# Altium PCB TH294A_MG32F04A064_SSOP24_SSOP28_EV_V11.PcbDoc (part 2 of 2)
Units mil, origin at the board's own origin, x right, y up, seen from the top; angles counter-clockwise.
Board outline 4724.41 x 2637.8 mil, 2 copper layers (Top Layer, Bottom Layer); 130 components, 100 nets, 562 pads, 309 vias.
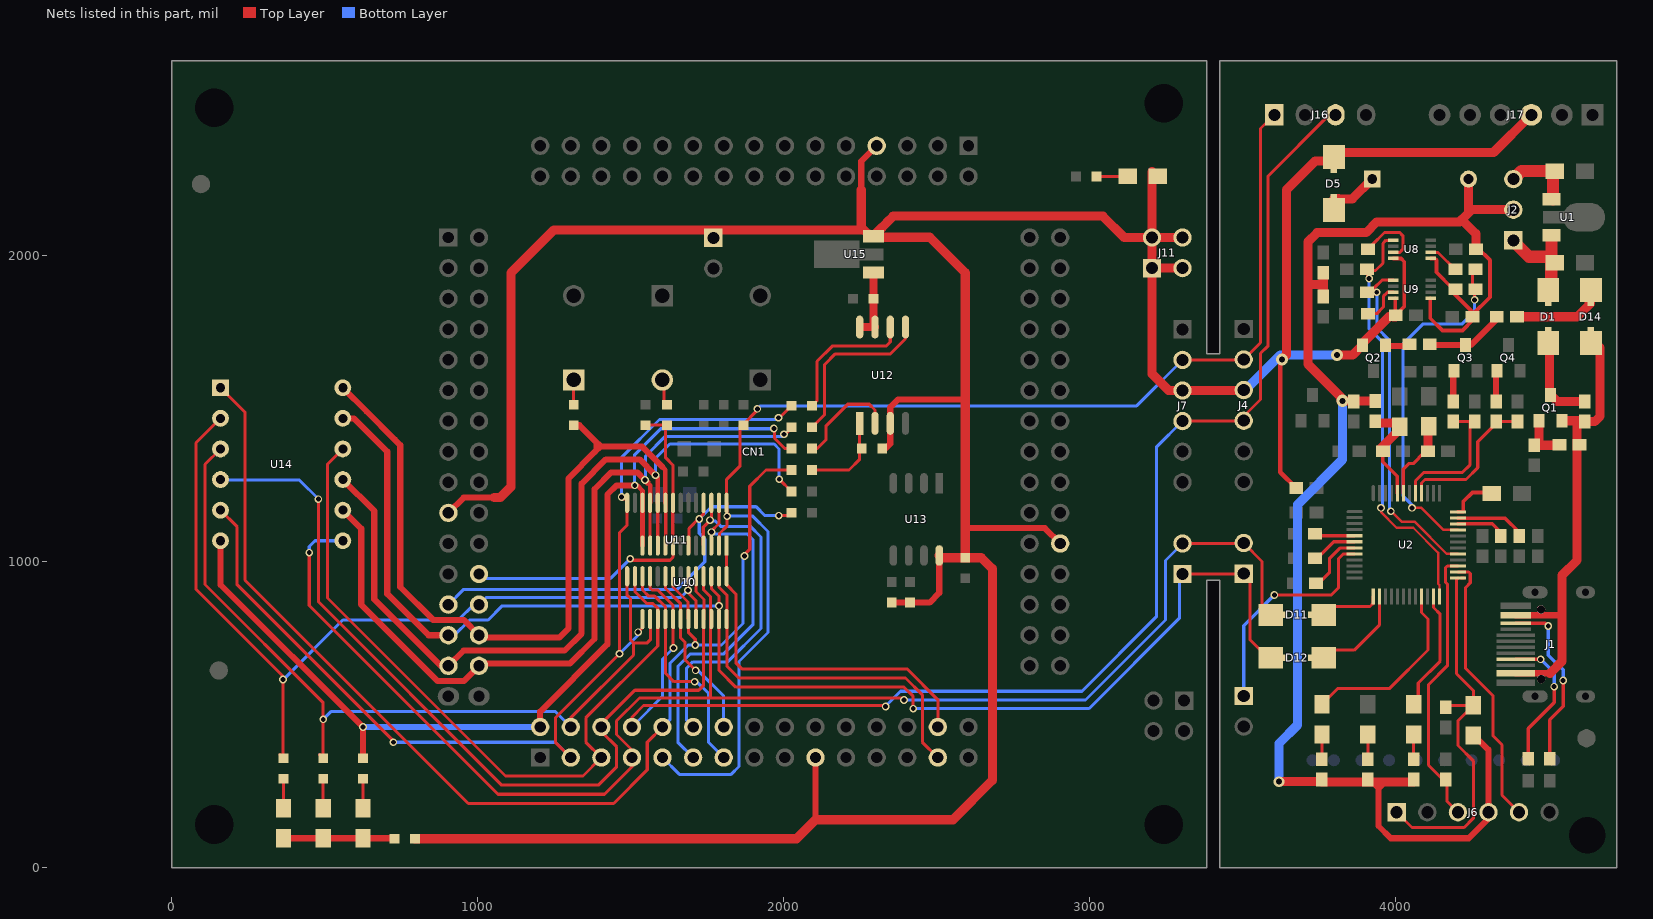
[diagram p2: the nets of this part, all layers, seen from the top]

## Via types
v1: diameter 20, hole 12, Top Layer to Bottom Layer, tented both sides, 221 vias
v2: diameter 25, hole 16, Top Layer to Bottom Layer, tented both sides, 61 vias
v3: diameter 30, hole 12, Top Layer to Bottom Layer, tented both sides, 13 vias
v4: diameter 25, hole 12, Top Layer to Bottom Layer, tented both sides, 6 vias
v5: diameter 40, hole 20, Top Layer to Bottom Layer, tented both sides, 3 vias
v6: diameter 30, hole 16, Top Layer to Bottom Layer, tented both sides, 2 vias
v7: diameter 15, hole 12, Top Layer to Bottom Layer, tented both sides, 1 vias
v8: diameter 35, hole 20, Top Layer to Bottom Layer, tented both sides, 1 vias
v9: diameter 28, hole 16, Top Layer to Bottom Layer, tented both sides, 1 vias

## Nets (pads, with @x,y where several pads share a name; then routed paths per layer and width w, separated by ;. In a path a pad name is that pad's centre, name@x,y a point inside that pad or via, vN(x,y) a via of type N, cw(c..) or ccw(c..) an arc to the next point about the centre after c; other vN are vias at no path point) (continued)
ICP/SWD_SDA: R41.1 R64.1 U2.33 | length 1167.1
  Top Layer w8: v2(4054.92,1176.26) 4085.92,1176.26 4157.82,1104.36 U2.33@4205.42,1104.36
  Top Layer w10: R64.1@4252.92,1966.26 4252.92,1956.26 4252.92,1891.26 4257.92,1886.26 4259.92,1884.26 v2(4259.92,1856.26)
  Bottom Layer w10: 4024.92,1506.26 4024.92,1496.26 ; v2@4052.92,1176.26 4052.92,1188.26 4024.92,1216.26 4024.92,1496.26 ; v2(4259.92,1856.26) 4259.92,1818.26 4219.39,1777.73 4091.39,1777.73 4024.92,1711.26 4024.92,1496.26
MLINK_RXD: CN1.7 D11.2 J5.2 J8.2 U10.22 U11.25 U14.7 | length 4926.9
  Top Layer w10: v2(450,1030) 450,856.91 1066.91,240 1415,240 1504.96,329.96 CN1.7@1504.96,360 1504.96,385.04 1454.41,435.59 1454.41,480 1529.41,555 2387.84,555 v2(2394.41,548.43) ; U11.25@1739.41,962.84 U11.25@1739.41,952.84 1739.41,907.84 1762.41,884.84 1762.41,812.84 1762.41,560 ; J8.2@3304.96,1060 J5.2@3504.96,1060 ; J5.2@3504.96,1061.26 3564.96,1001.26 3564.96,826.26 D11.2@3564.96,811.26
  Bottom Layer w10: v2(450,1030) 450,1050 468.9,1068.9 U14.7@559.92,1068.9 ; v2(2394.41,548.43) 2987.84,548.43 3249.41,810 3249.41,1004.45 J8.2@3304.96,1060
MLINK_TXD: CN1.117 D12.1 J5.1 J8.1 U10.23 U11.26 U14.11 | length 4671.1
  Top Layer w8: J5.1@3504.96,961.26 J5.1@3510.73,955.49
  Top Layer w10: U11.26@1764.41,952.84 1764.41,912.84 1789.41,887.84 v2(1789.41,856) U10.23@1789.41,812.84 1789.41,645 1844.41,590 2394.41,590 2424.41,560 v2(2424.41,520.15) ; J8.1@3304.96,960 J5.1@3504.96,960 ; J5.1@3524.96,959.26 3524.96,746.26 D12.1@3578.35,692.87
  Top Layer w20: U14.11@559.92,1468.9 596.1,1468.9 705,1360 705,1080 ; 705,1183.82 705,1080 ; CN1.117@904.96,760 840,760 705,895 705,1080
  Bottom Layer w10: CN1.117@904.96,775.55 CN1.117@904.96,760 924.41,760 974.41,810 1035,810 1081,856 v2(1789.41,856) ; v2(2424.41,520.15) 2999.56,520.15 3294.41,815 ; 3294.41,880 3294.41,815 ; J8.1@3294.41,949.45 3294.41,815
NetC2_2: C2.2 Q1.1 R5.2 | length 165
  Top Layer w30: R5.2@4454.96,1381.26 R5.2@4469.96,1381.26 ; Q1.1@4469.96,1461.26 R5.2@4469.96,1381.26 ; C2.2@4539.96,1381.26 4536.92,1381.26 R5.2@4469.96,1381.26
NetC6_1: C6.1 C7.2 R10.2 U2.44 | length 332.7
  Top Layer w11: C7.2@3959.92,1361.26 3959.92,1327.26 4007.15,1280.03 U2.44@4007.15,1224.39
  Top Layer w30: R10.2@3949.96,1453.26 4014.92,1453.26 C6.1@4014.92,1442.05 4014.92,1433.26 3953.92,1372.26 C7.2@3953.92,1367.26
NetC8_2: C8.2 C9.1 U2.43 | length 251
  Top Layer w11: U2.43@4026.84,1224.39 4026.84,1303.18 4044.92,1321.26 4058.92,1321.26 4095.42,1357.76 4106.92,1357.76 C8.2@4110.42,1357.76
  Top Layer w30: C8.2@4106.92,1361.26 C9.1@4106.92,1427.31
NetC11_1: C11.1 U2.36 | length 149.7
  Top Layer w12: U2.36@4205.42,1163.42 4222.12,1163.42 4222.12,1195.94 4252.82,1226.65 C11.1@4309.86,1226.65
NetD1_1: D1.1 Q1.3 R1.2 | length 276.4
  Top Layer w30: D1.1@4504.92,1699.65 4504.92,1548.24 Q1.3@4507.96,1545.2 4528.9,1524.26 R1.2@4619.96,1524.26
NetD2_1: D2.1 R6.2 | length 80.8
  Top Layer w10: R6.2@3760.51,354.52 D2.1@3760.51,435.31
NetD3_1: D3.1 R9.2 | length 80.8
  Top Layer w10: R9.2@4060.51,354.52 D3.1@4060.51,435.31
NetD4_1: D4.1 R11.2 | length 80.8
  Top Layer w10: R11.2@3910.51,354.52 D4.1@3910.51,435.31
NetD5_1: D5.1 SW1.1 | length 154.2
  Top Layer w30: D5.1@3799.92,2187.18 3815.85,2187.18 3814.92,2186.26 3859.96,2186.26 SW1.1@3924.96,2251.26
NetD8_1: D8.1 D9.1 D10.1 R58.1 | length 364.8
  Top Layer w20: D8.1@365.67,96.06 D9.1@495.67,96.06 D10.1@625.67,96.06 728.91,96.06 R58.1@730.47,96.06
NetD8_2: D8.2 R54.2 | length 96.5
  Top Layer w10: D8.2@365.67,194.49 R54.2@365.67,290.99
NetD9_2: D9.2 R55.2 | length 96.5
  Top Layer w10: D9.2@495.67,194.49 R55.2@495.67,290.99
NetD10_2: D10.2 R56.2 | length 96.5
  Top Layer w10: D10.2@625.67,194.49 R56.2@625.67,290.99
NetD11_1: D11.1 U2.13 | length 188.6
  Top Layer w10: D11.1@3766.57,854 3917.96,854 3928.41,864.45 U2.13@3928.41,886.91
NetD12_2: D12.2 U2.14 | length 296
  Top Layer w10: D12.2@3779.96,711 3866.06,711 3948.1,793.04 U2.14@3948.1,886.91
NetD13_2: D13.2 R43.2 | length 102.3
  Top Layer w10: R43.2@3023.46,2260 D13.2@3125.75,2260
NetD14_2: D14.2 R17.1 | length 272.5
  Top Layer w30: R17.1@4397.92,1801.26 4594.92,1801.26 D14.2@4639,1845.33 ; D14.2@4628.07,1869.41 D14.2@4639.92,1869.41 ; D14.2@4634,1845.33 D14.2@4634.92,1846.26
NetJ1_A5: J1.A5 R26.1 | length 460.3
  Top Layer w11: J1.A5@4393.76,681.16 v2(4475.51,681.16) ; R26.1@4434.96,356 4434.96,455 4519.96,540 v2@4519.96,592
  Bottom Layer w11: v2(4475.51,681.16) 4519.51,637.16 v2(4519.51,592)
NetJ1_B5: J1.B5 R27.2 | length 582.9
  Top Layer w11: J1.B5@4393.76,799.27 4491.24,799.27 v2(4500.51,790) ; R27.2@4504.96,356 4504.96,483 4548.96,527 v2(4548.96,612)
  Bottom Layer w11: v2(4500.51,790) 4500.51,695 4548.96,646.55 v2(4548.96,612)
NetQ2_1: Q2.1 R18.2 | length 72
  Top Layer w20: Q2.1@3967.92,1705.2 R18.2@4039.92,1705.2
NetQ3_1: Q3.1 R19.2 | length 97.5
  Top Layer w20: R19.2@4189.96,1524.26 Q3.1@4189.96,1621.79
NetQ3_2: Q3.2 R17.2 R18.1 | length 242.2
  Top Layer w20: R18.1@4132.95,1708.23 Q3.2@4230.46,1708.23 4246.89,1708.23 4331.92,1793.26 R17.2@4331.92,1801.26
NetQ4_1: Q4.1 R23.2 | length 97.5
  Top Layer w20: R23.2@4329.96,1524.26 Q4.1@4329.96,1621.79
NetR15_1: R15.1 U2.35 | length 263.6
  Top Layer w12: U2.35@4205.42,1142.73 4234.96,1142.73 ; 4267.22,1142.73 4234.96,1142.73 ; R15.1@4405.51,1084.26 4405.51,1096.26 4359.04,1142.73 4234.96,1142.73
NetR16_1: R16.1 U2.34 | length 163.6
  Top Layer w12: U2.34@4205.42,1124.05 4317.72,1124.05 4345.51,1096.26 R16.1@4345.51,1084.26
NetR29_2: R29.2 U8.7 | length 202.9
  Top Layer w10: R29.2@3924.92,2036.26 3964.92,2076.26 4014.92,2076.26 4024.92,2066.26 4024.92,2021.26 4015.08,2011.42 U8.7@3993.9,2011.42 U8.7@3991.78,2011.42
NetR30_2: R30.2 U9.7 | length 132.5
  Top Layer w10: R30.2@3910.92,1811.26 3939.92,1811.26 3961.42,1832.76 3961.42,1867.76 3975.08,1881.42 U9.7@3993.9,1881.42
NetR59_1: R59.1 SW4.2 | length 80.9
  Top Layer w10: R59.1@1609.41,1513.5 SW4.2@1609.41,1594.41
NetR61_2: R61.2 SW3.1 | length 80.9
  Top Layer w10: R61.2@1314.41,1513.5 SW3.1@1314.41,1594.41
NetR64_2: R64.2 U8.2 | length 108.2
  Top Layer w10: U8.2@4115.94,2011.42 4139.76,2011.42 R64.2@4195.92,1955.26 ; R64.2@4183.42,1969.76 R64.2@4186.92,1966.26
P44: J6.5 U2.26 | length 900.8
  Top Layer w10: U2.26@4205.42,966.57 4240.2,966.57 4245.51,961.26 4245.51,931.26 4230.51,916.26 4230.51,651.26 4320.51,561.26 4320.51,430.26 4349.06,401.71 4349.06,237.16 J6.5@4404.96,181.26
P45: J6.3 R25.1 U2.27 | length 931.6
  Top Layer w10: R25.1@4169.24,291.98 4169.24,288.26 4169.24,216.98 J6.3@4204.96,181.26 ; R25.1@4170.51,293.26 4165.51,293.26 4150.95,293.26 4108.96,335.25 4108.96,598.45 4170.51,660 4170.51,927.26 4163.92,933.85 4163.92,979.67 4170.5,986.25 U2.27@4205.42,986.25 ; J6.3@4206.24,182.54 J6.3@4213.51,175.26
PA0: CN1.114 R59.2 R60.1 U10.8 U11.8 | length 1204
  Top Layer w10: CN1.114@1004.96,960 1017.99,960 CN1.114@1016.2,958.21 ; v2(1499.41,1010) 1499.41,1005 1629.41,1005 1639.41,1015 U10.8@1639.41,1052.84 ; R60.1@1549.41,1446.5 1609.41,1446.5 R59.2@1610,1445.91 ; R59.2@1610,1448.91 1610,1446.5 R59.2@1610,1445.91 ; R59.2@1615,1446.5 R59.2@1615,1440.91 ; U10.8@1638.41,1052.84 U11.8@1638.41,1192.84 ; U11.8@1639.41,1192.84 1639.41,1315.59 1615,1340 R59.2@1615,1440.91 ; R59.2@1610,1445.91 1614.41,1441.5 R59.2@1615,1440.91
  Bottom Layer w10: CN1.114@1004.96,960 1018.96,946 1435.41,946 v2(1499.41,1010)
PA1: CN1.115 R69.2 U10.6 U11.4 | length 1557.5
  Top Layer w10: U10.6@1692,1030 1692,1052.84 1692,1109.5 1723.75,1141.25 1739.41,1156.91 U11.4@1739.41,1192.84 ; v2(1985,1151) 2026.5,1151 R69.2@2028,1151
  Bottom Layer w10: CN1.115@904.96,860 954.96,910 1652.91,910 1743,1000.09 1743,1075 1725,1093 v2(1725,1140) 1765,1180 1911,1180 1940,1151 v2(1985,1151)
PA2: CN1.116 R54.1 U10.20 U11.23 U14.2 | length 2881.7
  Top Layer w10: U14.2@159.92,1468.9 80,1388.98 80,910 364.41,625.59 v2(364.41,615) R54.1@364.41,359.25 ; R54.1@354.41,369.25 R54.1@364.41,359.25 ; R54.1@365.67,357.99 R54.1@364.41,359.25 ; U11.23@1689.41,962.84 U11.23@1689.41,952.84 1689.41,907 1689.41,897.84 1714.41,872.84 U10.20@1714.41,812.84
  Bottom Layer w10: v2@364.57,614.84 559.73,810 937.41,810 987.41,860 CN1.116@1004.96,860 1027.96,883 1664.41,883 v2(1688.41,907)
PA4: CN1.118 R61.1 U10.9 U11.9 U14.12 | length 2770.8
  Top Layer w10: 1384.11,1359.11 1384.11,1395.45 ; U10.9@1615.41,1052.84 U11.9@1615.41,1192.84
  Top Layer w15: 1605.41,1309.59 1614.41,1300.59 U11.9@1614.41,1192.84
  Top Layer w20: U14.12@559.92,1568.9 637.17,1491.65 ; 730,1398.82 637.17,1491.65 ; CN1.118@1004.96,752.43 1267.43,752.43 1297.72,782.72 1297.72,1272.72 1384.11,1359.11 1402.28,1377.28 ; CN1.118@1004.96,760 954.96,810 855,810 747.43,917.57 747.43,1381.39 637.17,1491.65 ; R61.1@1314.41,1446.5 1333.06,1446.5 1384.11,1395.45 1402.28,1377.28 ; 1605.41,1309.59 1537.72,1377.28 1402.28,1377.28
PA5: CN1.119 R68.2 U10.10 U11.10 U14.9 | length 2914.7
  Top Layer w10: U10.10@1589.41,1052.84 U11.10@1589.41,1192.84 ; v2(1986.5,1270) R68.2@2026.5,1230
  Top Layer w15: v2@1573.5,1291.5 v2(1581.78,1283.22) 1589.41,1275.59 U11.10@1589.41,1192.84
  Top Layer w20: U14.9@559.92,1268.9 662.57,1166.25 662.57,877.43 880,660 CN1.119@904.96,660 954.96,710 1285,710 1340.15,765.15 1340.15,1255.15 1419.85,1334.85 1530.15,1334.85 v2@1580,1285
  Bottom Layer w10: v2@1581.44,1283.22 1581.44,1337.56 1628.88,1385 1970,1385 1986,1369 v2@1986,1270
PA6: CN1.120 R73.2 U10.11 U11.11 U14.8 | length 2770.1
  Top Layer w10: CN1.120@1004.96,653.84 CN1.120@998.8,653.84 ; CN1.120@1004.96,660 CN1.120@998.8,653.84 ; CN1.120@1004.96,662.95 1002.01,662.95 992.9,653.84 CN1.120@998.8,653.84 ; U10.11@1563.41,1052.84 U11.11@1563.41,1192.84 ; v2@2000,1415 2002,1415 2005,1415 R73.2@2020,1430
  Top Layer w15: v2@1549,1265 1564.41,1249.59 U11.11@1564.41,1192.84
  Top Layer w20: U14.8@559.92,1168.9 620.15,1108.67 620.15,859.85 870,610 954.96,610 CN1.120@998.8,653.84 ; CN1.120@1022.57,667.57 1302.57,667.57 1382.57,747.57 1382.57,1237.57 1437.43,1292.43 1522.57,1292.43 v2(1547.56,1267.44) v2@1555,1260
  Bottom Layer w10: v2@1549,1265 1549,1267.44 1549,1345 1614,1410 1997,1410 v2@2002,1415 ; v2@1999.5,1419.5 v2@2000,1420
  other v2: 2002,1417
PA7: CN1.2 R56.1 R74.2 U10.12 U11.12 U14.6 | length 3364.4
  Top Layer w10: U11.12@1539.41,1192.84 1539.41,1230 ; v2@1971,1435 1971,1404 2005,1370 R74.2@2026.5,1370
  Top Layer w15: v2@1521.76,1250 1539.41,1232.36 U11.12@1539.41,1192.84 U10.12@1539.41,1052.84
  Top Layer w20: U14.6@159.92,1068.9 159.92,925.08 625,460 v2(625.67,460) R56.1@625.67,357.99 ; CN1.2@1204.96,460 1204.96,509.96 1425,730 1425,1220 1455,1250 v2@1514,1250
  Bottom Layer w10: v2(1514,1249.75) 1514,1350 1599,1435 v2@1969,1435
  Bottom Layer w20: v2@630.02,460 CN1.2@1204.96,460
  other v2: 1969,1436
PA8: CN1.3 R72.2 U10.13 U11.14 U14.5 | length 3471.2
  Top Layer w10: U14.5@159.92,1168.9 214.41,1114.41 214.41,925 v2@724.7,414.7 ; CN1.3@1304.96,360 1254.41,410.55 1254.41,489.41 v2(1464.41,699.41) 1464.41,1095 1489.41,1120 U11.14@1489.41,1192.84 1489.41,1205 v2@1471.41,1205 ; v2(1525,770) 1539.41,784.41 U10.13@1539.41,812.84 ; v2@1983.75,1467.25 1985.75,1469.25 R72.2@2026.5,1510
  Bottom Layer w10: v2@720,410 v2(725,410) 1254.96,410 CN1.3@1304.96,360 ; v2(1464.41,699.41) 1525,760 v2(1525,770) ; v2(1471.41,1212) 1471.41,1341.41 1595,1465 v2@1982,1465
  other v2: 1984,1471
PA9: CN1.4 R55.1 U10.14 U11.15 U14.3 | length 2781.6
  Top Layer w10: U14.3@159.92,1368.9 109.41,1318.39 109.41,925.59 495.67,539.33 v2(495.67,485) R55.1@495.67,357.99 R55.1@484.41,369.25 ; R55.1@505.67,347.99 R55.1@505.67,357.99 ; CN1.4@1304.96,460 1304.96,489.96 1510,695 1510,735 ; U11.15@1489.41,962.84 U11.15@1489.41,952.84 1489.41,890.59 1500,880 1500,745 1510,735 ; U10.14@1564.41,812.84 1565,812.25 1565,745 1555,735 1510,735
  Bottom Layer w10: v2(495.67,485) 520.67,510 1254.96,510 CN1.4@1304.96,460
PA10: CN1.5 U10.15 U11.16 U14.10 | length 2432.5
  Top Layer w10: U14.10@559.92,1368.9 510,1318.98 510,881.76 1091.76,300 1344.96,300 CN1.5@1404.96,360 1354.41,410.55 1354.41,490 1589.41,725 U10.15@1589.41,812.84 1589.41,847.84 1573.41,863.84 1553.41,863.84 1514.41,902.84 U11.16@1514.41,952.84 U11.16@1514.41,962.84
PA11: CN1.6 U10.21 U11.24 U14.4 | length 2846.4
  Top Layer w10: v2(480,1205) 480,869.34 1079.34,270 1395,270 1455,330 1455,395 1404.96,445.04 CN1.6@1404.96,460 1404.96,470.55 1514.41,580 1723,580 1739.41,596.41 U10.21@1739.41,812.84 ; U11.24@1714.41,952.84 1714.41,902.84 1740.41,876.84 1740.41,812.84 U10.21@1740.41,811
  Bottom Layer w10: U14.4@159.92,1266.9 418.1,1266.9 v2(480,1205)
PA13_SWDIO: CN1.8 J4.4 J7.4 J16.3 U10.17 U11.18 | length 4480.6
  Top Layer w10: CN1.8@1504.96,460 1504.96,491.96 1543,530 v2@2334.41,530 ; U11.18@1564.41,962.84 U11.18@1564.41,952.84 1564.41,913.84 1570.41,907.84 1589.41,907.84 1639.41,857.84 U10.17@1639.41,812.84 v2@1639.41,718 ; J7.4@3304.96,1460 J4.4@3489.96,1460 ; J4.4@3497.96,1468.26 3559.96,1530.26 3559.96,1681.26 3584.96,1706.26 3584.96,2261.3 3784.92,2461.26 J16.3@3804.96,2461.26
  Bottom Layer w10: CN1.8@1504.96,460 CN1.8@1509.96,465 ; CN1.8@1509.96,460 CN1.8@1509.96,465 ; v2(1641,718) 1605,682 1605,560.04 CN1.8@1509.96,465 ; v2@2335.19,529.22 2382.69,576.72 2976.13,576.72 3219.41,820 3219.41,1374.45 J7.4@3304.96,1460
  other v2: 2334.41,527
PA14_SWCLK: CN1.9 J4.2 J7.2 J16.1 R65.1 U10.2 U11.1 | length 4239.6
  Top Layer w10: U10.2@1791,1055.84 1791,1092.59 1815,1116.59 1815,1149 1815,1192.25 U11.1@1814.41,1192.84 1814.41,1269.41 1858.71,1313.71 1858.71,1443.71 R65.1@1865.75,1450.75 ; R65.1@1865.75,1445.75 1868.25,1448.25 v2@1915,1495 ; J7.2@3304.96,1660 J4.2@3504.96,1660 ; J4.2@3504.96,1661.26 3559.96,1716.26 3559.96,2416.26 J16.1@3604.96,2461.26
  Bottom Layer w10: CN1.9@1604.96,360 1659.96,305 1829.41,305 1855,330.59 1855,674 1950,769 1950,1099 1900,1149 v2(1816,1149) ; v2(1915,1500) 1925,1510 3154.96,1510 J7.2@3304.96,1660
PA15: CN1.10 R71.2 U10.19 U11.21 U14.1 | length 3875.4
  Top Layer w10: U14.1@159.92,1568.9 240,1488.82 240,940 970,210 1445,210 1555,320 1555,410.04 CN1.10@1604.96,460 ; U11.21@1639.41,962.84 U11.21@1639.41,952.84 1639.41,917.84 1688.41,868.84 U10.19@1688.41,815 ; U10.19@1689.41,812.84 1689.41,769.59 1712,747 v2(1712,728) ; v2@1868,1019 1870.5,1021.5 1890,1041 1890,1247 1943,1300 R71.2@2026.5,1300
  Bottom Layer w10: CN1.10@1604.96,460 1630,485.04 1630,669 1689,728 v2(1712,728) 1798,728 1868,798 v2@1868,1019
  other v2: 1873,1019
PASS: D3.2 U2.23 | length 394.2
  Top Layer w10: D3.2@4075.51,531.26 4075.51,533.73 4075.51,603.55 4146.96,675 4146.96,829 4125.26,850.7 U2.23@4125.26,886.91
PB0: CN1.11 U10.3 U11.2 | length 1218.8
  Top Layer w10: CN1.11@1704.96,335.55 CN1.11@1704.96,360 ; U10.3@1764.41,1052.84 1764.41,1097 1764.41,1100 1789.41,1125 U11.2@1789.41,1192.84
  Bottom Layer w10: CN1.11@1704.96,360 1655,409.96 1655,658 1694.87,697.87 1803.87,697.87 1900,794 1900,1073 1882,1091 1771,1091 v2(1765,1097)
PB1: CN1.12 U10.4 U11.3 | length 1173.5
  Top Layer w10: U10.4@1739.41,1052.84 1738,1054.25 1738,1113 1760.5,1135.5 1764.41,1139.41 U11.3@1764.41,1192.84
  Bottom Layer w10: CN1.12@1694.41,470.55 CN1.12@1704.96,460 ; CN1.12@1704.96,479.45 CN1.12@1704.96,460 ; v2@1758,1133 1760,1133 1778,1133 1795,1116 1892,1116 1927,1081 1927,782 1818,673 1704,673 1684,653 1684,480.96 CN1.12@1704.96,460
  other v2: 1760,1136
PB2: CN1.13 U10.16 U11.17 | length 788.7
  Top Layer w10: U11.17@1539.41,962.84 U11.17@1539.41,952.84 1539.41,907.84 1559.41,887.84 1579.41,887.84 1614.41,852.84 U10.16@1614.41,812.84 1614.41,635.59 1642,608 1703,608 1706.5,611.5 v2@1710,615 ; CN1.13@1804.96,345.55 CN1.13@1804.96,360
  Bottom Layer w10: v2@1710,615 1713.5,611.5 1755,570 1755,409.96 CN1.13@1804.96,360
  other v2: 1710,608
PB3: CN1.14 U10.18 U11.20 | length 584.6
  Top Layer w10: U11.20@1614.41,962.84 U11.20@1614.41,952.84 1614.41,912.84 1664.41,862.84 U10.18@1664.41,812.84 1664.41,750.59 1679,736 1679,679 v2@1712.5,645.5 ; v2@1712.5,645 v2@1712.5,645.5 ; v2(1713,645) v2@1712.5,645.5
  Bottom Layer w10: v2@1717,649 1804.96,561.04 CN1.14@1804.96,460
PB4: CN1.27 U10.24 U11.27 | length 1218.5
  Top Layer w10: U11.27@1789.41,962.84 U11.27@1789.41,952.84 1789.41,916.84 1816.41,889.84 1816.41,812.84 1816.41,658 1854.41,620 2399.41,620 2454.41,565 2454.41,410.55 CN1.27@2504.96,360
PB5: CN1.28 U10.1 U11.28 | length 1187.4
  Top Layer w10: U10.1@1814.41,1045 U11.28@1814.41,952.84 1814.41,925 1844.41,895 1844.41,670 1864.41,650 2404.41,650 2504.96,549.45 CN1.28@2504.96,460
RST: C12.2 J6.1 R22.2 U2.25 | length 1228.1
  Top Layer w10: J6.1@4004.96,181.26 4054.96,131.26 4225.51,131.26 4255.51,161.26 4255.51,349.26 4205.51,399.26 4205.51,480.47 C12.2@4255.51,530.47 ; R22.2@4171.72,530.47 C12.2@4255.51,530.47 ; U2.25@4205.51,946.26 4200.51,941.26 4200.51,634.26 4255.51,579.26 C12.2@4255.51,530.47 ; U2.25@4214.96,946.88 U2.25@4224.34,946.88
RST_CTRL_51: R19.1 R20.1 U2.41 | length 451.6
  Top Layer w10: U2.41@4066.21,1224.39 4066.21,1264.55 4092.92,1291.26 4218.66,1291.26 4244.96,1317.56 R20.1@4244.96,1458.26 ; R19.1@4189.96,1458.26 R20.1@4244.96,1458.26 ; R20.1@4259.96,1458.26 R20.1@4244.96,1458.26
RST_CTRL_ARM: R23.1 R24.1 U2.40 | length 474.1
  Top Layer w10: U2.40@4085.89,1224.39 4085.89,1257.4 4097.76,1269.26 4231.66,1269.26 4269.96,1307.56 4269.96,1392.56 R23.1@4327.42,1450.02 ; R23.1@4329.96,1458.26 R24.1@4399.96,1458.26
SPI_CLK: R72.1 U12.6 | length 466.6
  Top Layer w10: R72.1@2093.5,1510 2110,1526.5 2110,1655.36 2159.64,1705 2335.73,1705 2349.41,1718.68 U12.6@2349.41,1767.48
SPI_MISO: R74.1 U12.2 | length 347.7
  Top Layer w10: R74.1@2093.5,1370 2110.01,1370 2140,1399.99 2140,1445 2210,1515 2280.73,1515 2299.41,1496.32 U12.2@2299.41,1452.52 U12.2@2299.41,1456.32
SPI_MOSI: R73.1 U12.5 | length 559.6
  Top Layer w10: R73.1@2093.5,1440 2135,1481.5 2135,1645 2170,1680 2350,1680 2399.41,1729.41 U12.5@2399.41,1767.48
SPI_NCS: R70.2 R71.1 U12.1 | length 290.9
  Top Layer w10: R71.1@2093.5,1300 2214.41,1300 2249.41,1335 2249.41,1362.91 R70.2@2256.5,1370 ; R70.2@2249.41,1370 U12.1@2249.41,1452.52
SWD_SCL_DIR: R63.2 U2.29 U9.5 | length 1149.4
  Top Layer w8: v2@3986.42,1165.76 4020.92,1131.26 4062.92,1131.26 4168.56,1025.62 U2.29@4205.42,1025.62
  Top Layer w10: R63.2@3918.92,1870.26 R63.2@3924.92,1876.26 ; R63.2@3919.92,1884.26 R63.2@3920.15,1883.9 ; R63.2@3922.39,1880.3 R63.2@3920.15,1883.9 ; R63.2@3922.85,1876.26 R63.2@3924.92,1876.26 ; v2@3941.85,1876.26 3939.92,1876.26 R63.2@3924.92,1876.26 ; U9.5@3993.9,1920.79 3957.03,1920.79 3928.71,1892.47 R63.2@3920.15,1883.9
  Bottom Layer w10: v2(3939.92,1881.26) 3939.92,1765.75 3980.92,1724.75 3980.92,1496.26 ; 3980.92,1506.26 3980.92,1496.26 ; v2@3990.92,1161.26 3986.42,1165.76 3980.92,1171.26 3980.92,1496.26
  other v2: 3985.92,1165.26
SWD_SDA_DIR: R62.2 U2.24 U8.5 | length 1381.2
  Top Layer w8: v2(3953.92,1176.26) 3953.92,1162.26 4004.92,1111.26 4058.92,1111.26 4140.92,1029.26 4140.92,928.26 4144.95,924.23 U2.24@4144.95,886.91
  Top Layer w10: v2@3909.92,1926.26 R62.2@3909.92,1952.26 ; R62.2@3911.92,1952.26 R62.2@3914.92,1952.26 ; R62.2@3914.92,1958.26 3914.92,1956.26 R62.2@3914.92,1952.26 ; U8.5@3993.9,2050.79 3969.45,2050.79 3959.92,2041.26 3959.92,1976.26 3935.92,1952.26 R62.2@3914.92,1952.26
  Bottom Layer w10: v2(3914.92,1926.26) 3914.92,1761.26 3958.92,1717.26 3958.92,1486.26 ; v2@3958.92,1176.26 3958.92,1486.26 ; 3958.92,1506.26 3958.92,1486.26
TOOL_OPTION0: R2.1 U2.5 | length 121.1
  Top Layer w10: R2.1@3747.96,1081.26 3751.88,1085.18 U2.5@3867.44,1085.18
TOOL_OPTION1: R3.1 U2.6 | length 142.8
  Top Layer w10: R3.1@3746.46,1012.8 3799.15,1065.49 U2.6@3867.44,1065.49
TOOL_OPTION2: R28.1 U2.7 | length 191.4
  Top Layer w10: R28.1@3750.96,930 3784.96,964 3784.96,1010 3820.77,1045.81 U2.7@3867.44,1045.81
USBOK: D2.2 U2.21 | length 605
  Top Layer w10: D2.2@3760.51,533.73 3813.04,586.26 3982.22,586.26 4107.59,711.63 4107.59,812.69 4085.89,834.39 U2.21@4085.89,886.91
VCC3: C20.2 U12.7 U12.8 U15.1 | length 230.9
  Top Layer w25: U12.8@2249.41,1767.48 U12.7@2294.41,1767.48 ; U12.7@2294.41,1765 U12.7@2294.41,1767.48 ; U15.1@2294.41,1945.94 C20.2@2294.41,1860 U12.7@2294.41,1767.48 ; U12.7@2299.41,1767.48 U12.7@2294.41,1767.48
VCC_USB: C2.1 D14.1 J1.A4 J1.A9 J1.M5 J1.M6 Q1.2 R1.1 | length 1456.2
  Top Layer w22: J1.A4@4393.76,635.87 4477.17,635.87 4506.59,635.87 ; J1.A9@4393.76,824.88 4477.17,824.88 4545.51,824.88
  Top Layer w30: 4506.59,635.87 4545.51,674.8 4545.51,824.88 4545.51,956.26 4594.84,1005.59 4594.84,1382.52 4594.84,1448.14 ; Q1.2@4544.96,1461.26 4596.96,1461.26 ; R1.1@4609.96,1458.26 R1.1@4619.96,1458.26 4651.92,1458.26 4669.92,1476.26 D14.1@4669.92,1699.65
VCP_OPTION: J3.1 U2.8 | length 845.4
  Top Layer w10: v2(3604.92,891.26) 3629.96,891.26 ; 3729.96,891.26 3629.96,891.26 ; U2.8@3867.44,1026.12 3831.08,1026.12 3814.96,1010 3814.96,915 3791.22,891.26 3629.96,891.26
  Bottom Layer w12: J3.1@3504.96,561.26 3504.96,791.3 v2(3604.92,891.26)
VDD: C12.1 J2.2 J6.4 R4.1 R6.1 R9.1 R10.1 R11.1 R12.1 R13.1 R14.2 R40.2 R41.2 SW1.2 U8.1 U9.1 | length 5168.8
  Top Layer w12: R11.1@3919.7,280.78 3920.22,280.26 3945.51,254.97 3945.86,254.62 ; 3945.87,252.91 3972.03,279.07 ; U9.1@4114.92,1861.73 4114.92,1796.26 4154.92,1756.26 4219.92,1756.26 4252.92,1789.26 R40.2@4252.92,1801.26 ; U8.1@4115.94,1991.73 4129.45,1991.73 4134.92,1986.26 4134.92,1946.26 ; 4134.92,1956.26 4134.92,1946.26 ; R40.2@4252.92,1799.26 R40.2@4252.92,1801.26 ; R40.2@4252.92,1806.26 R40.2@4252.92,1801.26 ; R40.2@4252.92,1816.26 4187.42,1881.76 4186.92,1882.26 4186.92,1891.26 4186.92,1894.26 4134.92,1946.26 ; R4.1@4269.92,2026.26 4309.92,1986.26 4309.92,1865.09 4252.92,1808.09 R40.2@4252.92,1801.26
  Top Layer w20: 3945.51,280.26 3945.51,254.97 3945.51,136.26 3985.51,96.26 4240.51,96.26 4304.96,160.71 J6.4@4304.96,181.26 4304.96,385.81 4265.51,425.26 C12.1@4265.51,432.05
  Top Layer w30: v8(3620.51,281.26) R6.1@3760.51,281.26 ; 3714.92,1646.26 3822.91,1538.27 v5@3822.91,1526.26 ; 3714.92,1646.9 3714.92,1906.26 ; R6.1@3760.51,280.26 3910.51,280.26 3920.22,280.26 3945.51,280.26 R9.1@4060.51,280.26 ; R12.1@3764.92,1867.26 3764.92,1906.26 ; R13.1@3764.92,1945.26 3764.92,1906.26 ; v5@3837.17,1525.52 3864.92,1525.52 R10.1@3934.92,1525.52 ; 4239.92,2151.26 SW1.2@4239.92,2251.26 ; R4.1@4263.92,2021.26 4263.92,2072.26 4217.42,2118.76 ; J2.2@4386.34,2151.26 4249.92,2151.26 4217.42,2118.76 ; 3714.92,1906.26 3714.92,2046.26 3744.92,2076.26 3904.92,2076.26 3939.92,2111.26 4209.92,2111.26 4217.42,2118.76 ; 3714.92,1906.26 3764.92,1906.26
  Bottom Layer w30: v8(3620.51,281.26) 3620.51,406.26 3680.51,466.26 3680.51,1186.81 3827.91,1334.21 v5(3827.91,1526.26)
VDD3: C5.1 J2.3 U1.1 | length 238.5
  Top Layer w40: J2.3@4386.34,2250.94 4412.6,2277.2 C5.1@4516.3,2277.2 ; U1.1@4516.3,2185.31 C5.1@4516.3,2277.2 ; C5.1@4522.09,2277.2 C5.1@4516.3,2277.2
VDD5: C4.1 D1.2 J2.1 U1.3 | length 287.7
  Top Layer w40: J2.1@4384.86,2049.47 4437.13,1997.2 4511.3,1997.2 U1.3@4511.3,2067.2 ; D1.2@4509.92,1902.87 C4.1@4509.92,1972.52
VDUT: C17.1 C19.1 CN1.19 CN1.39 CN1.67 CN1.109 D5.2 D13.1 J4.3 J7.3 J11.1 J11.2 J11.3 J11.4 J17.3 JP3.1 Q2.2 R7.1 R58.2 R66.2 R67.2 R70.1 U8.8 U9.8 U12.3 U13.8 U15.3 | length 12918.6
  Top Layer w12: U8.8@3993.9,1991.73 4019.45,1991.73 4029.92,1981.26 4029.92,1834.26 C17.1@4001.92,1806.26 ; U9.8@3999.92,1861.73 3999.92,1806.26 C17.1@4000.92,1805.26
  Top Layer w15: v5@3624.92,1661.9 3624.92,1661.26 3624.92,1293.26 R7.1@3676.92,1241.26
  Top Layer w20: CN1.109@904.96,1160 954.96,1210 1054.96,1210 ; 2104.96,157 CN1.19@2104.96,360 ; 2254.41,2160 2254.41,2309.45 CN1.67@2304.96,2360 ; R70.1@2328.5,1365 2349.41,1385.91 U12.3@2349.41,1452.52 2349.41,1505 2374.41,1530 2589.41,1530 ; R67.2@2354.41,866.5 R66.2@2414.41,866.5 2477.91,866.5 2509.58,898.18 U13.8@2509.58,1020.63 ; 2594.41,1110 2854.96,1110 CN1.39@2904.96,1060
  Top Layer w30: R58.2@795.91,94.83 2042.79,94.83 2104.96,157 2554.41,157 2683.41,286 2683.41,977 2646.91,1013.5 C19.1@2594.41,1013.5 ; 1054.96,1210 1074.41,1210 1109.41,1245 1109.41,1944.41 1250,2085 JP3.1@1770.96,2085 ; JP3.1@1770.96,2059.08 JP3.1@1770.96,2085 ; 2254.41,2215 2254.41,2093.44 ; U15.3@2287.91,2059.94 2254.41,2093.44 ; U15.3@2294.41,2065 2355.35,2125.94 ; U15.3@2298.46,2060.94 2478.46,2060.94 2594.41,1945 2594.41,1110 C19.1@2594.41,1013.5 ; 2337.31,2107.91 2359.4,2130 3044.41,2130 3114.41,2060 J11.2@3204.96,2060 ; U13.8@2509.58,1020.63 2516.71,1013.5 C19.1@2594.41,1013.5 ; 2594.41,1070 C19.1@2594.41,1013.5 ; D13.1@3204.96,2275 3204.96,2260 J11.2@3204.96,2060 ; J11.3@3304.96,1960 J11.1@3204.96,1960 ; J11.4@3304.96,2060 J11.2@3204.96,2060 ; J4.3@3504.96,1560 J7.3@3304.96,1560 3259.41,1560 3204.96,1614.45 J11.1@3204.96,1960 ; v5@3629.89,1661.29 3644.92,1676.32 3644.92,2216.26 3738.98,2310.31 3799.02,2310.31 3805.75,2317.05 3826.57,2337.87 4321.57,2337.87 J17.3@4444.96,2461.26 ; v5(3809.92,1676.26) 3860.95,1676.26 Q2.2@3892.92,1708.23 ; Q2.2@3889.91,1711.24 C17.1@3979.92,1801.26 ; C17.1@3994.92,1801.26 C17.1@4001.92,1801.26 ; JP3.1@1770.96,2085 2254.41,2085 2254.41,2093.44 ; J11.1@3204.96,1960 J11.2@3204.96,2060
  Bottom Layer w30: J4.3@3506.81,1558.15 3507.44,1558.78 3619.92,1671.26 3624.92,1676.26 3629.92,1676.26 v5(3809.92,1676.26)
  other v5: 3629.92,1661.26
pads on no net: CN1.1 CN1.15 CN1.16 CN1.18 CN1.20 CN1.21 CN1.22 CN1.23 CN1.24 CN1.25 CN1.26 CN1.29 CN1.30 CN1.31 CN1.32 CN1.33 CN1.34 CN1.35 CN1.36 CN1.37 CN1.38 CN1.40 CN1.42 CN1.43 CN1.44 CN1.45 CN1.46 CN1.47 CN1.48 CN1.49 CN1.50 CN1.51 CN1.52 CN1.53 CN1.54 CN1.55 CN1.56 CN1.57 CN1.58 CN1.59 CN1.60 CN1.61 CN1.62 CN1.63 CN1.64 CN1.65 CN1.66 CN1.68 CN1.70 CN1.71 CN1.72 CN1.73 CN1.74 CN1.75 CN1.76 CN1.77 CN1.78 CN1.79 CN1.80 CN1.81 CN1.82 CN1.83 CN1.84 CN1.85 CN1.86 CN1.87 CN1.88 CN1.89 CN1.90 CN1.91 CN1.92 CN1.93 CN1.94 CN1.95 CN1.96 CN1.97 CN1.98 CN1.99 CN1.100 CN1.101 CN1.102 CN1.103 CN1.104 CN1.105 CN1.106 CN1.108 CN1.110 CN1.111 CN1.112 CN1.113 CN1.121 CN1.122 J1.A8 J1.B8 J6.6 J7.1 U2.1 U2.2 U2.3 U2.4 U2.28 U2.30 U2.32 U2.37 U2.38 U2.39 U2.46 U8.3 U8.6 U9.3 U9.6 U11.6 U11.13 U11.19

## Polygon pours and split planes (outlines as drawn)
GND_POWER on Bottom Layer "Top Layer-No Net" (solid, remove dead copper, pour order 1001): 16,22.05 4701.52,22.05 4701.52,2612.05 16,2612.05
GND_POWER on Top Layer "Top Layer-No Net" (solid, remove dead copper, pour order 1001): 14.41,21.26 4699.92,21.26 4699.92,2611.26 14.41,2611.26

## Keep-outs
Top Layer:
  circle w5: c95.92,2234.68 r59.06
  circle w5: c154.41,645 r59.06
  circle w5: c4625.51,423.16 r59.06
Keep-Out Layer:
  circle w7.88: c140,2484.68 r133.86
  circle w7.88: c3243.31,2499.06 r133.86
  circle w7.88: c3243.31,141.26 r133.86
  circle w7.88: c140,141.26 r133.86
  lines w15: 3426.61,940 3383.31,940 3383.31,1.26 -314.96,1.26 -314.96,2639.06 3383.31,2639.06 3383.31,1680 3426.61,1680 ; 4724.41,2.52 4724.41,2640.31 4724.41,2.52

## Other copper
Top Layer:
  pour cut-out: 3339.92,2625 3459.92,2625 3459.92,1.26 3339.92,1.26
Bottom Layer:
  pour cut-out: 3339.92,2626.26 3459.92,2626.26 3459.92,1.26 3339.92,1.26

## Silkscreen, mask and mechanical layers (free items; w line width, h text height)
Top Overlay:
  circle w10: c140,141.26 r137.8
  circle w4: c3243.31,141.26 r137.8
  circle w10: c3243.31,2499.06 r137.8
  circle w10: c140,2484.68 r137.8
  region: 3634.36,1069.3 3587.46,1094.95 3589.36,1079.3 3559.96,1079.3 3559.96,1059.3 3589.36,1059.3 3587.46,1044.95
  region: 3560.91,957.12 3607.82,931.47 3605.91,947.12 3634.96,947.12 3634.96,967.12 3605.91,967.12 3607.82,981.47
  region: 3507.04,265.31 3532.69,337.21 3517.04,335.31 3517.04,395.31 3497.04,395.31 3497.04,335.31 3482.69,337.21
  region: 3244.32,1060.55 3197.42,1086.2 3199.32,1070.55 3149.32,1070.55 3149.32,1050.55 3199.32,1050.55 3197.42,1036.2
  region: 3150.87,948.37 3197.78,922.72 3195.87,938.37 3245.87,938.37 3245.87,958.37 3195.87,958.37 3197.78,972.72
  lines w10: 704.41,618 834.41,618 ; 1069.41,618 1199.41,618 ; 1069.41,718 1199.41,718 ; 1069.41,923 1199.41,923 ; 1114.41,528 1244.41,528
  text "When J16 Open" at 3449.92,2581.26 h45
  text "2026.09" at 1134.41,2550 h35
  text "SW1 must be off" at 3449.92,2521.9 h45
  text "GND" at 2224.96,2425 h50 r90
  text "VDUT" at 2324.96,2425 h50 r90
  text "RST" at 4049.86,2416.26 h37 r90
  text "GND" at 4099.86,2416.26 h37 r90
  text "TH294A_MG32F04A064" at 304.41,2370 h50
  text "Power" at 4014.92,2351.26 h45
  text "Off" at 3880.82,2349.58 h45
  text "On" at 4234.92,2346.26 h45
  text "SCL" at 4559.92,2326.26 h35 r90
  text "CLK" at 4664.92,2326.26 h35 r90
  text "SDA" at 4369.86,2321.26 h37 r90
  text "VCC" at 4459.92,2321.26 h37 r90
  text "SSOP24_SSOP28_EV_V11" at 214.41,2270 h50
  text "VDD3" at 4324.92,2196.26 h37 r90
  text "Power" at 3079.96,2160 h50
  text "U10 U11 current" at 1223,2121 h45
  text "VDD" at 4234.92,2116.26 h37
  text "measurement" at 1227,2065 h45
  text "VDD5" at 4204.92,2061.26 h37
  text "SR420361N" at 99.41,1940 h50
  text "Key2" at 1200,1935 h50
  text "Key1" at 1500,1935 h50
  text "RESET" at 1845,1935 h50
  text "VDUT" at 3144.96,1841.9 h50
  text "SCL" at 3159.96,1645 h33
  text "VDUT" at 3124.96,1540 h33
  text "SPI Flash" at 2185,1475 h50 r90
  text "SDA" at 3154.96,1445 h33
  text "GND" at 3154.96,1340 h33
  text "RST" at 3159.96,1240 h33
  text "GND" at 714.96,1230 h50
  text "GND" at 2969.96,1140 h50
  text "PA12_TX" at 3119.92,1136.26 h38
  text "VDUT" at 674.92,1131.9 h50
  text "VDUT" at 2969.96,1035 h50
  text "PA0" at 1069.86,935 h50
  text "PA3_RX" at 3129.92,851.26 h38
  text "PA2" at 1069.96,831.9 h50
  text "PA1" at 724.96,830 h50
  text "I2C EERPOM" at 2305,820 h50 r90
  text "PA4" at 1069.96,731.9 h50
  text "PA3" at 704.96,730 h50
  text "PA6" at 1069.96,631.9 h50
  text "PA5" at 704.96,630 h50
  text "PA7" at 1114.92,541.26 h50
  text "IO with underline" at 34.41,525 h50
  text "PA9" at 1324.96,525 h50 r90
  text "PA11" at 1424.96,525 h50 r90
  text "PA13" at 1499.96,525 h50 r90
  text "PA15" at 1624.96,525 h50 r90
  text "PB1" at 1700,525 h50 r90
  text "PB3" at 1829.96,525 h50 r90
  text "PB5" at 2529.96,525 h50 r90
  text "is high sink pin." at 29.41,420 h50
  text "GND" at 3174.92,321.26 h50
  text "J3" at 3464.96,203.16 h45
  text "PB0" at 1729.96,170 h50 r90
  text "PB2" at 1829.96,170 h50 r90
  text "GND" at 2034.96,170 h50 r90
  text "PB4" at 2529.96,170 h50 r90
  text "PB6" at 2629.96,170 h50 r90
  text "PA8" at 1324.96,165 h50 r90
  text "Open Disable VCP." at 3445.51,131.26 h40
  text "Open Disable VCP." at 3445.51,131.26 h40
  text "VDUT" at 2129.96,125.71 h50 r90
  text "PA10" at 1424.96,125 h50 r90
  text "PA12" at 1529.92,121.26 h50 r90
  text "PA14" at 1634.92,121.26 h50 r90
  text "Short Enable VCP." at 3445.51,36.26 h40
  text "Short Enable VCP." at 3445.51,36.26 h40
Mechanical 1:
  circle w7.88: c3404.96,1615 r27
  circle w7.88: c3404.96,1505 r27
  circle w7.88: c3404.96,1418 r25
  circle w7.88: c3404.96,1300 r25
  circle w7.88: c3404.96,1010 r33
  lines w7.88: 3383.31,1080 3383.31,1234 3426.61,1234 3426.61,1080 3383.31,1080
  lines w8.88: 0,0 0,2637.8 3383.31,2637.8 3383.31,1680 3426.61,1680 3426.61,2637.8 4724.41,2637.8 4724.41,0 3426.61,0 3426.61,940 3383.31,940 3383.31,0 0,0
Mechanical 2:
  lines w6: 3404.96,1033 3404.96,1010 3427.96,1010 ; 3404.96,1323 3404.96,1300 3427.96,1300 ; 3404.96,1443 3404.96,1420 3427.96,1420 ; 3404.96,1528 3404.96,1505 3427.96,1505 ; 3404.96,1638 3404.96,1615 3427.96,1615

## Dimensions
0,0 to 0,2637.8 on Top Overlay
0,0 to 4724.41,0 on Top Overlay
